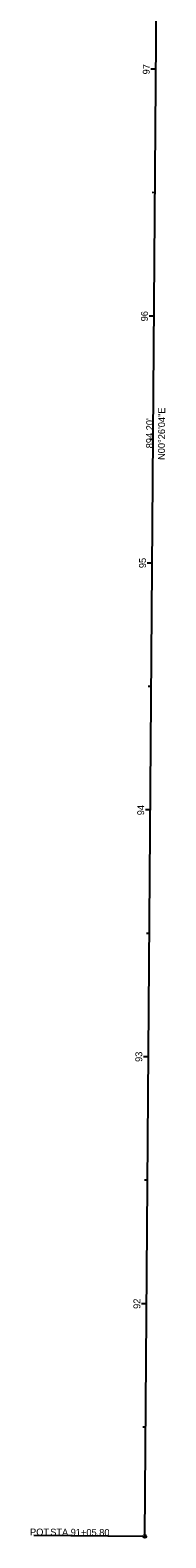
# Model space of a CAD drawing. Extents: x 217610 to 217676, y 457884 to 460293.
# Drawn here: x 217610 to 217665, y 457884 to 458495 of the extents above; entities that cross this region are included whole.
import ezdxf

# ---------------------------------------------------------------- set-up
doc = ezdxf.new("R2010")
doc.units = 0
for name, color, linetype in [('RW_X_CL', 7, 'Continuous'), ('RW_X_CL_100_Bearings', 7, 'Continuous'), ('RW_X_CL_100_Cardinal_Points', 7, 'Continuous'), ('RW_X_CL_100_Distances', 7, 'Continuous'), ('RW_X_CL_100_Stations', 7, 'Continuous'), ('RW_X_CL_500_Bearings', 7, 'Continuous'), ('RW_X_CL_500_Cardinal_Points', 7, 'Continuous'), ('RW_X_CL_500_Distances', 7, 'Continuous'), ('RW_X_CL_500_Stations', 7, 'Continuous')]:
    doc.layers.add(name, color=color, linetype=linetype)

msp = doc.modelspace()

# ---------------------------------------------------------------- linework, layer by layer
at = {"layer": 'RW_X_CL'}
msp.add_line((217656.36, 457884.99), (217663.13, 458779.17), dxfattribs=at)
at = {"layer": 'RW_X_CL_100_Cardinal_Points'}
msp.add_line((217656.36, 457884.99), (217611.36, 457885.33), dxfattribs=at)
msp.add_circle((217656.36, 457884.99), 0.6, dxfattribs=at)
at = {"layer": 'RW_X_CL_100_Stations'}
for p, q in [((217660.86, 458479.17), (217658.86, 458479.19)), ((217660.48, 458429.18), (217659.28, 458429.19)), ((217660.1, 458379.18), (217658.1, 458379.19)), ((217659.72, 458329.18), (217658.52, 458329.19)), ((217659.34, 458279.18), (217657.34, 458279.2)), ((217658.96, 458229.18), (217657.76, 458229.19)), ((217658.59, 458179.18), (217656.59, 458179.2)), ((217658.21, 458129.18), (217657.01, 458129.19)), ((217657.83, 458079.19), (217655.83, 458079.2)), ((217657.45, 458029.19), (217656.25, 458029.2)), ((217657.07, 457979.19), (217655.07, 457979.2)), ((217656.69, 457929.19), (217655.49, 457929.2))]:
    msp.add_line(p, q, dxfattribs=at)
at = {"layer": 'RW_X_CL_500_Cardinal_Points'}
msp.add_line((217656.36, 457884.99), (217611.36, 457885.33), dxfattribs=at)
msp.add_circle((217656.36, 457884.99), 0.6, dxfattribs=at)
at = {"layer": 'RW_X_CL_500_Stations'}
for p, q in [((217660.86, 458479.17), (217659.66, 458479.18)), ((217660.1, 458379.18), (217658.9, 458379.19)), ((217659.34, 458279.18), (217657.34, 458279.2)), ((217658.59, 458179.18), (217657.39, 458179.19)), ((217657.83, 458079.19), (217656.63, 458079.2)), ((217657.07, 457979.19), (217655.87, 457979.2))]:
    msp.add_line(p, q, dxfattribs=at)

# ---------------------------------------------------------------- texts
at = {"layer": 'RW_X_CL_100_Bearings'}
msp.add_text('N00°26\'04"E', height=2.8, rotation=89.56567, dxfattribs=at).set_placement((217664.46, 458320.93))
at = {"layer": 'RW_X_CL_100_Cardinal_Points'}
for s, p in [('POT', (217609.87, 457885.38)), (' STA. ', (217617, 457885.33)), ('91+05.80', (217626.33, 457885.26))]:
    msp.add_text(s, height=2.8, rotation=359.56567, dxfattribs=at).set_placement(p)
at = {"layer": 'RW_X_CL_100_Distances'}
msp.add_text("894.20'", height=2.8, rotation=89.56567, dxfattribs=at).set_placement((217659.66, 458325.64))
at = {"layer": 'RW_X_CL_100_Stations'}
for s, p in [('97', (217658.34, 458477.07)), ('96', (217657.59, 458377.06)), ('95', (217656.83, 458277.11)), ('94', (217656.07, 458177.04)), ('93', (217655.31, 458077.12)), ('92', (217654.55, 457977.11))]:
    msp.add_text(s, height=2.8, rotation=89.56567, dxfattribs=at).set_placement(p)
at = {"layer": 'RW_X_CL_500_Bearings'}
msp.add_text('N00°26\'04"E', height=2.8, rotation=89.56567, dxfattribs=at).set_placement((217664.46, 458320.93))
at = {"layer": 'RW_X_CL_500_Cardinal_Points'}
for s, p in [('POT', (217609.87, 457885.38)), (' STA. ', (217617, 457885.33)), ('91+05.80', (217626.33, 457885.26))]:
    msp.add_text(s, height=2.8, rotation=359.56567, dxfattribs=at).set_placement(p)
at = {"layer": 'RW_X_CL_500_Distances'}
msp.add_text("894.20'", height=2.8, rotation=89.56567, dxfattribs=at).set_placement((217659.66, 458325.64))
at = {"layer": 'RW_X_CL_500_Stations'}
msp.add_text('95', height=2.8, rotation=89.56567, dxfattribs=at).set_placement((217656.83, 458277.11))

doc.saveas('drawing.dxf')
